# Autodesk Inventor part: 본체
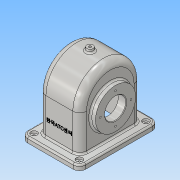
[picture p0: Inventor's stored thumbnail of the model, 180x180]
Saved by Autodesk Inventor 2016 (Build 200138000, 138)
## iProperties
Created: 2018-08
Part Number: 본체
Material: 알루미늄 6061
Document SubType Name: Modeling
Designer: Administrator
Density: 2.7 g/cm^3
Appearance: 알루미늄 - 평지
Mass: 1091.9 g
Surface Area: 1182.65 cm^2
Volume: 404.407 cm^3
Author: Administrator
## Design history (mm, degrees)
sketch "스케치1"
  geometry: L1 (-55, 75)-(55, 75); L2 (55, 75)-(55, -75); L3 (55, -75)-(-55, -75); L4 (-55, -75)-(-55, 75); L5 (-55, 75)-(55, -75); L6 (55, 75)-(-55, -75); 1 further point
  constraints: 12 end point, 2 midpoint, 2 parallel, 1 horizontal, 1 perpendicular
  dimensions: "d0" = 110 distance of L2.end L3.end; "d1" = 150 distance of L1.end L2.end
extrude "돌출1" new body sketch "스케치1" distance "d2" = 10; taper "d3" = 0 deg
sketch "스케치2"
  geometry: L1 (75, 10)-(-75, 10) reference; L2 (-58, 10)-(-58, 78); L3 (-58, 78)-(58, 78); L4 (58, 78)-(58, 10); L5 (-58, 10)-(58, 10); L6 (-75, 0)-(75, 0) reference; A1 r 58 centre (0, 78) between (58, 78) and (-58, 78); 2 further points
  constraints: 8 end point, 2 midpoint, 2 perpendicular, 2 point on circle, 2 point on line, 1 centre point, 1 collinear, 1 vertical, 1 vertical alignment
  dimensions: "d4" = 58 radius of A1; "d5" = 78 distance from line of L6 A1.centre
extrude "돌출2" join sketch "스케치2" stored distance "d6" = 77; taper "d7" = 0 deg
sketch "스케치3"
  geometry: L1 (58, 10)-(-58, 10) reference; L2 (58, 10)-(58, 78) reference; L3 (-58, 78)-(-58, 10) reference; L4 (52, 78)-(52, 16); L5 (52, 16)-(-52, 16); L6 (-52, 16)-(-52, 78); L7 (52, 16)-(52, 0); L8 (75, 0)-(-75, 0) reference; L9 (-52, 16)-(-52, 0); L10 (-52, 0)-(52, 0); A1 r 58 centre (0, 78) between (58, 78) and (-58, 78) reference; A2 r 52 centre (0, 78) between (52, 78) and (-52, 78); 1 further point
  constraints: 12 end point, 2 point on circle, 2 point on line, 1 centre point, 1 collinear, 1 parallel, 1 vertical, 3 other
  dimensions: "d8" = 6 radial gap between concentric circles of A1 A2
extrude "돌출3" cut sketch "스케치3" stored distance "d9" = 67; taper "d10" = 0 deg
sketch "스케치4"
  geometry: L1 (0, -75)-(0, 75) reference; C1 r 38 at (65, 0); 2 further points
  constraints: 1 centre point, 1 horizontal alignment, 1 midpoint
  dimensions: "d11" = 76 diameter of C1; "d12" = 65 distance from line of L1 C1.centre
extrude "돌출4" join sketch "스케치4" distance "d13" = 5; taper "d14" = 0 deg
sketch "스케치5"
  geometry: L1 (0, 75)-(0, -75) reference; C1 r 38 at (-65, 0); 2 further points
  constraints: 1 centre point, 1 horizontal alignment, 1 midpoint
  dimensions: "d15" = 76 diameter of C1; "d16" = 65 distance from line of L1 C1.centre
extrude "돌출5" join sketch "스케치5" distance "d17" = 10; taper "d18" = 0 deg
hole "구멍1" diameter "d21" = 40; stored, may be unused: countersink angle "d25" = 90 deg, drill point angle "d27" = 0 deg; dims "d19" = 10, "d20" = 10, "d22" = 6, "d23" = 4, "d24" = 2, "d26" = 8
node "작업 평면1"
sketch "스케치6"
  geometry: L1 (-93.86, 0)-(93.86, 0); L2 (-33.5, 52)-(-33.5, -52) reference; L3 (-33.5, 20)-(-19.5, 20); L4 (-43.5, 20)-(-33.5, 20) reference; L5 (-19.5, 20)-(-19.5, 28); L6 (-19.5, 28)-(-33.5, 39.747); L7 (-33.5, 39.747)-(-33.5, 20); L8 (0, 123.05)-(0, -125.497); 2 further points
  constraints: 12 end point, 3 point on line, 2 collinear, 1 coincident, 1 horizontal, 1 midpoint, 1 perpendicular, 1 vertical
  dimensions: "d29" = 40 diameter of L3 L1; "d30" = 50 deg angle of L5 L6; "d31" = 24 distance of L4.start L3.end; "d32" = 56 diameter of L5.end L1
revolve "회전1" sketch "스케치6" stored, may be unused: angle "d33" = 90 deg
sketch "스케치7"
  geometry: L1 (0, 0)-(0, 29); C1 r 28 at (0, 0) reference; 2 further points
  constraints: 2 end point, 1 coincident, 1 vertical
  dimensions: "d34" = 29 distance of L1.start L1.end
hole "구멍2" sketch "스케치7" at (0, 29) diameter "d35" = 3.242; stored, may be unused: countersink angle "d39" = 90 deg, drill point angle "d41" = 118 deg; dims "d36" = 8, "d37" = 4, "d38" = 2, "d40" = 10
sketch "스케치8"
  geometry: 1 further point
sketch "스케치9"
  geometry: L1 (0, 0)-(-29, 0); C1 r 38 at (0, 0) reference; 2 further points
  constraints: 2 end point, 1 coincident, 1 horizontal
  dimensions: "d45" = 29 distance of L1.start L1.end
hole "구멍3" sketch "스케치9" at (-29, 0) diameter "d46" = 3.242; stored, may be unused: countersink angle "d50" = 90 deg, drill point angle "d52" = 118 deg; dims "d47" = 8, "d48" = 4, "d49" = 2, "d51" = 10
node "작업 평면2"
sketch "스케치10"
  geometry: C1 r 6 at (0, 0); 1 further point
  constraints: 1 centre point, 1 coincident
  dimensions: "d57" = 12 diameter of C1
extrude "돌출6" join sketch "스케치10" distance "d58" = 10; taper "d59" = 5 deg
hole "구멍4" diameter "d62" = 4.459; stored, may be unused: countersink angle "d66" = 90 deg, drill point angle "d68" = 118 deg; dims "d60" = 10, "d61" = 10, "d63" = 10, "d64" = 4, "d65" = 2, "d67" = 12.8
fillet "모깎기1" dims "d69" = 13
fillet "모깎기2" dims "d70" = 12
fillet "모깎기3" dims "d71" = 3
chamfer "모따기1" distance "d72" = 1; stored, may be unused: second distance "d73" = 2, angle "d74" = 45 deg
hole "구멍5" diameter "d77" = 5; stored, may be unused: countersink angle "d81" = 90 deg, drill point angle "d83" = 0 deg; dims "d75" = 10, "d76" = 10, "d78" = 10, "d79" = 12, "d80" = 4, "d82" = 10
sketch "스케치11"
  geometry: L1 (-17.5, -78)-(-29.5, -78) reference; L2 (-13, 0)-(-13, -65) reference; 2 further points
  constraints: 1 other
  dimensions: "d84" = 40 distance from line of L1 point (25.5, -38); "d85" = 38.5 distance from line of L2 point (25.5, -38)
feature "엠보싱1" sketch "스케치11" dims "d0" = 110, "d1" = 150, "d86" = 0.5, "d87" = 0
fillet "모깎기4" dims "d88" = 8
sketch "스케치12"
  geometry: L1 (74.643, 169.124)-(-74.643, 169.124); L2 (-74.643, 169.124)-(-74.643, -25.89); L3 (-74.643, -25.89)-(74.643, -25.89); L4 (74.643, -25.89)-(74.643, 169.124); L5 (74.643, 169.124)-(-74.643, -25.89); L6 (-74.643, 169.124)-(74.643, -25.89); 2 further points
  constraints: 12 end point, 2 midpoint, 2 parallel, 1 horizontal, 1 perpendicular
extrude "돌출7" cut sketch "스케치12" stored distance "d89" = 10; taper "d90" = 0 deg
node "솔리드1"
pattern_circular "원형 패턴1" dims angle "d43" = 360 deg
pattern_circular "원형 패턴2" dims angle "d54" = 360 deg
mirror "대칭2"
mirror "대칭3"
node "투영된 루프1"
other parameters: "d28" = 65, "d56" = 142
